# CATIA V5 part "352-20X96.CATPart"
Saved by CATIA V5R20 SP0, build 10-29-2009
Part number: 352-20X96
Definition: NONE
Nomenclature: 352-20X96
Source: Unknown
Description: 352-20X96
Bounding box of the stored display mesh (mm): x 0 to 96, y -14 to 14, z -14 to 14
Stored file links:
  C:\Users\Utente\Desktop\IO LAVORO\3D X SITO CF\X SITO\PLASTICA\352\352-20X96.CATPart
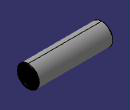
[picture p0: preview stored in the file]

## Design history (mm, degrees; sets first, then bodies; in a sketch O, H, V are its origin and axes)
Body1 "352-20X96" (main body)
  Solid1: solid without history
